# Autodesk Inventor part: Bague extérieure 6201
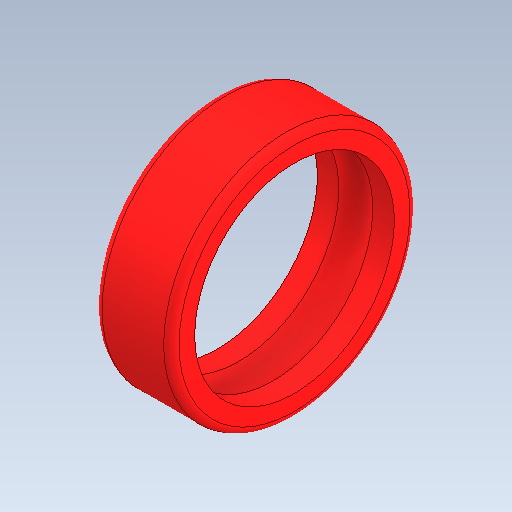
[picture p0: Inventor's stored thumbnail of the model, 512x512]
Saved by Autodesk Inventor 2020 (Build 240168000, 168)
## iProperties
Created: 2003-06
Part Number: Bague extérieure 6201
Material: Générique
Document SubType Name: Modeling
Designer: Bruno
Density: 1 g/cm^3
Appearance: Par défaut
Author: Bruno
Sending System: SolidWorks 2011
Last Author: frederic
Last Saved: 2012-02-20
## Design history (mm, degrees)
feature "Base-Révolution"
node "Solide1"
